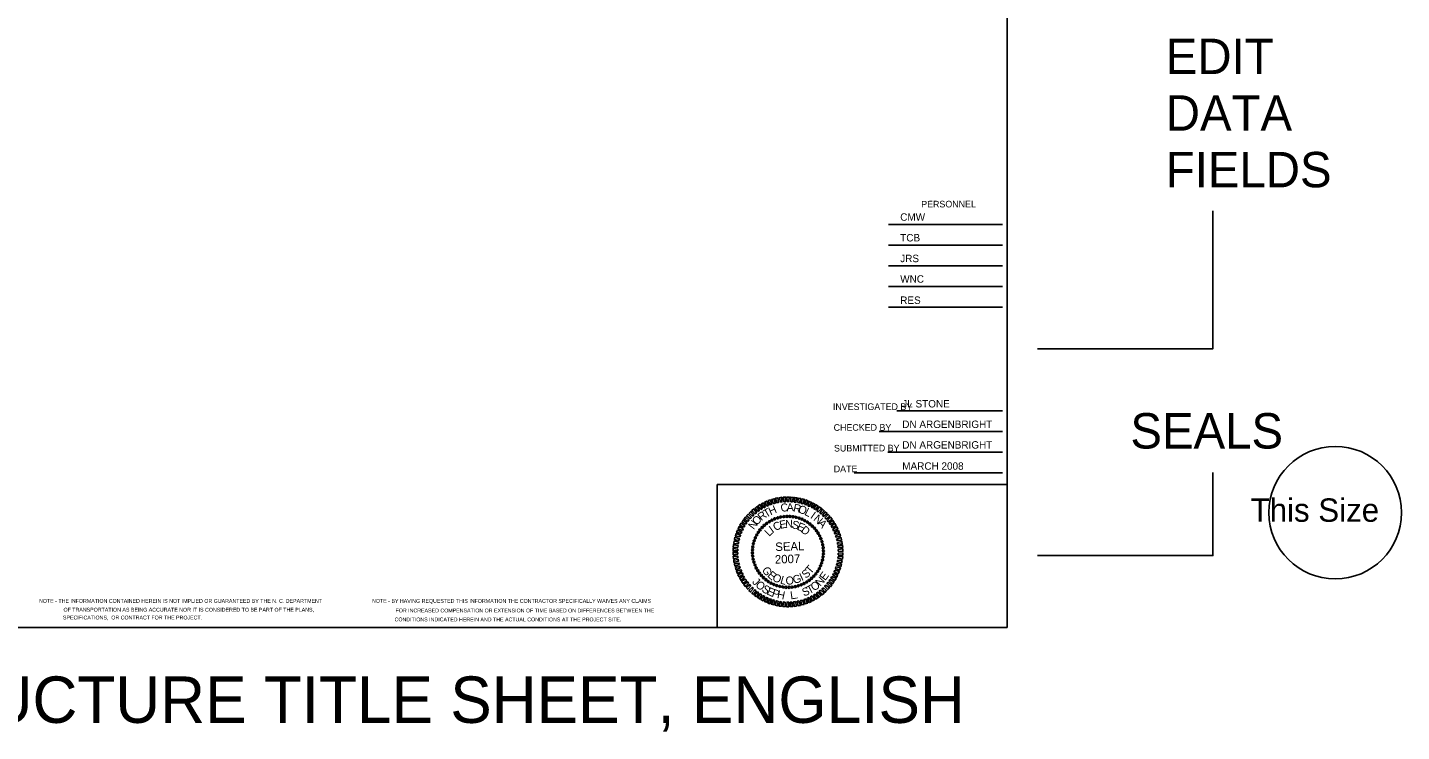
# Model space of a CAD drawing. Extents: x 278710 to 279187, y 171464 to 171625.
# Drawn here: x 278796.7 to 278951.9, y 171464.3 to 171543.9 of the extents above; entities that cross this region are included whole.
import ezdxf

# ---------------------------------------------------------------- set-up
doc = ezdxf.new("R2010")
doc.units = 0
for name, color, linetype in [('Geotech Sheets and Borders Cell', 7, 'Continuous'), ('Old_Level_2', 7, 'Continuous'), ('Old_Level_3', 7, 'Continuous'), ('Old_Level_4', 7, 'Continuous'), ('Old_Level_5', 7, 'Continuous')]:
    doc.layers.add(name, color=color, linetype=linetype)

msp = doc.modelspace()

# ---------------------------------------------------------------- linework, layer by layer
at = {"layer": 'Geotech Sheets and Borders Cell'}
for p, q in [((278893.94, 171521.62), (278906.83, 171521.62)), ((278893.94, 171519.28), (278906.83, 171519.28)), ((278893.94, 171516.94), (278906.83, 171516.94)), ((278893.94, 171514.6), (278906.83, 171514.6)), ((278893.94, 171512.26), (278906.83, 171512.26)), ((278894.89, 171500.56), (278906.83, 171500.56)), ((278892.9, 171498.21), (278906.83, 171498.21)), ((278893.87, 171495.87), (278906.83, 171495.87)), ((278890.07, 171493.53), (278906.83, 171493.53))]:
    msp.add_line(p, q, dxfattribs=at)
for points in [[(278756.09, 171580.95), (278907.34, 171580.95), (278907.34, 171476.08), (278756.09, 171476.08)], [(278907.34, 171492.21), (278874.6, 171492.21), (278874.6, 171476.08), (278907.34, 171476.08)]]:
    msp.add_lwpolyline(points, close=True, dxfattribs=at)
for points in [[(278930.6, 171523.15), (278930.6, 171507.57), (278910.78, 171507.57)], [(278930.6, 171493.58), (278930.6, 171484.19), (278910.78, 171484.19)]]:
    msp.add_lwpolyline(points, dxfattribs=at)
msp.add_circle((278944.41, 171489.04), 7.49, dxfattribs=at)
at = {"layer": 'Old_Level_2'}
for p, q in [((278879.66, 171487.36), (278879.66, 171487.36)), ((278879.9, 171487.61), (278879.9, 171487.61)), ((278880.17, 171487.82), (278880.17, 171487.82)), ((278880.47, 171488.03), (278880.47, 171488.03)), ((278880.78, 171488.19), (278880.78, 171488.19)), ((278881.1, 171488.34), (278881.1, 171488.34)), ((278881.43, 171488.45), (278881.43, 171488.45)), ((278881.77, 171488.54), (278881.77, 171488.54)), ((278882.11, 171488.6), (278882.11, 171488.6)), ((278882.47, 171488.62), (278882.47, 171488.62)), ((278882.82, 171488.62), (278882.82, 171488.62)), ((278883.16, 171488.58), (278883.16, 171488.58)), ((278883.5, 171488.52), (278883.5, 171488.52)), ((278883.85, 171488.43), (278883.85, 171488.43)), ((278884.17, 171488.3), (278884.17, 171488.3)), ((278884.48, 171488.15), (278884.48, 171488.15)), ((278884.79, 171487.96), (278884.79, 171487.96)), ((278885.08, 171487.77), (278885.08, 171487.77)), ((278885.33, 171487.54), (278885.33, 171487.54)), ((278885.59, 171487.28), (278885.59, 171487.28)), ((278878.77, 171485.87), (278878.77, 171485.87)), ((278878.9, 171486.19), (278878.9, 171486.19)), ((278879.04, 171486.51), (278879.04, 171486.51)), ((278879.24, 171486.81), (278879.24, 171486.81)), ((278879.43, 171487.1), (278879.43, 171487.1)), ((278885.81, 171487.01), (278885.81, 171487.01)), ((278886, 171486.72), (278886, 171486.72)), ((278886.16, 171486.42), (278886.16, 171486.42)), ((278886.32, 171486.1), (278886.32, 171486.1)), ((278886.43, 171485.77), (278886.43, 171485.77)), ((278878.57, 171484.49), (278878.57, 171484.49)), ((278878.58, 171484.84), (278878.58, 171484.84)), ((278878.6, 171484.13), (278878.6, 171484.13)), ((278878.61, 171485.19), (278878.61, 171485.19)), ((278878.68, 171485.53), (278878.68, 171485.53)), ((278882.59, 171484.61), (278882.59, 171484.61)), ((278886.52, 171485.43), (278886.52, 171485.43)), ((278886.57, 171485.09), (278886.57, 171485.09)), ((278886.6, 171484.73), (278886.6, 171484.73)), ((278886.6, 171484.38), (278886.6, 171484.38)), ((278878.66, 171483.79), (278878.66, 171483.79)), ((278878.74, 171483.45), (278878.74, 171483.45)), ((278878.86, 171483.12), (278878.86, 171483.12)), ((278879.01, 171482.8), (278879.01, 171482.8)), ((278886.13, 171482.71), (278886.13, 171482.71)), ((278886.27, 171483.03), (278886.27, 171483.03)), ((278886.41, 171483.34), (278886.41, 171483.34)), ((278886.49, 171483.69), (278886.49, 171483.69)), ((278886.55, 171484.04), (278886.55, 171484.04)), ((278879.17, 171482.49), (278879.17, 171482.49)), ((278879.36, 171482.21), (278879.36, 171482.21)), ((278879.58, 171481.93), (278879.58, 171481.93)), ((278879.83, 171481.68), (278879.83, 171481.68)), ((278880.09, 171481.45), (278880.09, 171481.45)), ((278880.38, 171481.25), (278880.38, 171481.25)), ((278880.68, 171481.07), (278880.68, 171481.07)), ((278884.39, 171481.02), (278884.39, 171481.02)), ((278884.7, 171481.2), (278884.7, 171481.2)), ((278884.99, 171481.39), (278884.99, 171481.39)), ((278885.26, 171481.61), (278885.26, 171481.61)), ((278885.51, 171481.86), (278885.51, 171481.86)), ((278885.74, 171482.12), (278885.74, 171482.12)), ((278885.94, 171482.41), (278885.94, 171482.41)), ((278881, 171480.92), (278881, 171480.92)), ((278881.32, 171480.79), (278881.32, 171480.79)), ((278881.66, 171480.7), (278881.66, 171480.7)), ((278882.01, 171480.64), (278882.01, 171480.64)), ((278882.36, 171480.6), (278882.36, 171480.6)), ((278882.7, 171480.6), (278882.7, 171480.6)), ((278883.06, 171480.62), (278883.06, 171480.62)), ((278883.41, 171480.68), (278883.41, 171480.68)), ((278883.75, 171480.77), (278883.75, 171480.77)), ((278884.08, 171480.88), (278884.08, 171480.88))]:
    msp.add_line(p, q, dxfattribs=at)
for points in [[(278880.21, 171489.77), (278879.97, 171490.24), (278880.2, 171490.34), (278880.39, 171489.84)], [(278880.57, 171489.92), (278880.37, 171490.4), (278880.61, 171490.48), (278880.74, 171489.99)], [(278880.96, 171490.05), (278880.76, 171490.54), (278881.04, 171490.62), (278881.13, 171490.1)], [(278881.34, 171490.16), (278881.18, 171490.66), (278881.45, 171490.7), (278881.53, 171490.19)], [(278881.73, 171490.22), (278881.62, 171490.73), (278881.88, 171490.78), (278881.91, 171490.26)], [(278882.12, 171490.28), (278882.06, 171490.8), (278882.32, 171490.81), (278882.32, 171490.28)], [(278882.51, 171490.29), (278882.47, 171490.81), (278882.74, 171490.81), (278882.7, 171490.3)], [(278882.91, 171490.28), (278882.91, 171490.81), (278883.18, 171490.77), (278883.1, 171490.27)], [(278883.28, 171490.24), (278883.35, 171490.76), (278883.6, 171490.72), (278883.48, 171490.22)], [(278883.71, 171490.17), (278883.75, 171490.69), (278884.03, 171490.65), (278883.88, 171490.14)], [(278884.08, 171490.09), (278884.18, 171490.59), (278884.44, 171490.53), (278884.26, 171490.04)], [(278884.45, 171489.97), (278884.61, 171490.48), (278884.85, 171490.38), (278884.65, 171489.92)], [(278878.32, 171488.36), (278877.91, 171488.67), (278878.09, 171488.87), (278878.46, 171488.49)], [(278878.58, 171488.66), (278878.21, 171488.99), (278878.4, 171489.18), (278878.72, 171488.77)], [(278878.88, 171488.91), (278878.52, 171489.29), (278878.73, 171489.46), (278879.04, 171489.03)], [(278879.17, 171489.17), (278878.87, 171489.56), (278879.07, 171489.73), (278879.35, 171489.27)], [(278879.51, 171489.39), (278879.19, 171489.8), (278879.44, 171489.95), (278879.66, 171489.49)], [(278879.86, 171489.59), (278879.58, 171490.02), (278879.82, 171490.15), (278880.03, 171489.68)], [(278884.83, 171489.82), (278885, 171490.31), (278885.25, 171490.2), (278885, 171489.74)], [(278885.2, 171489.66), (278885.4, 171490.12), (278885.64, 171490), (278885.35, 171489.57)], [(278885.52, 171489.46), (278885.79, 171489.93), (278886, 171489.78), (278885.7, 171489.38)], [(278885.86, 171489.24), (278886.13, 171489.69), (278886.36, 171489.52), (278886.01, 171489.14)], [(278886.19, 171489), (278886.48, 171489.44), (278886.68, 171489.25), (278886.34, 171488.89)], [(278886.48, 171488.74), (278886.8, 171489.13), (278887.01, 171488.95), (278886.6, 171488.61)], [(278886.77, 171488.46), (278887.12, 171488.84), (278887.3, 171488.64), (278886.9, 171488.31)], [(278877.44, 171487.04), (278876.98, 171487.22), (278877.07, 171487.46), (278877.52, 171487.21)], [(278877.61, 171487.39), (278877.15, 171487.61), (278877.3, 171487.85), (278877.73, 171487.55)], [(278877.84, 171487.73), (278877.4, 171487.98), (278877.53, 171488.21), (278877.93, 171487.88)], [(278878.06, 171488.04), (278877.63, 171488.34), (278877.79, 171488.54), (278878.17, 171488.2)], [(278887.03, 171488.16), (278887.4, 171488.52), (278887.57, 171488.29), (278887.14, 171488.01)], [(278887.25, 171487.84), (278887.66, 171488.17), (278887.82, 171487.94), (278887.37, 171487.69)], [(278887.48, 171487.5), (278887.9, 171487.81), (278888.03, 171487.56), (278887.57, 171487.36)], [(278887.66, 171487.17), (278888.12, 171487.42), (278888.22, 171487.19), (278887.74, 171487)], [(278876.98, 171485.53), (278876.47, 171485.57), (278876.52, 171485.84), (278877.02, 171485.71)], [(278877.05, 171485.91), (278876.55, 171486), (278876.59, 171486.27), (278877.11, 171486.09)], [(278877.15, 171486.31), (278876.65, 171486.43), (278876.75, 171486.68), (278877.23, 171486.48)], [(278877.29, 171486.67), (278876.79, 171486.83), (278876.9, 171487.08), (278877.37, 171486.85)], [(278887.82, 171486.81), (278888.29, 171487.03), (278888.39, 171486.79), (278887.9, 171486.64)], [(278887.97, 171486.42), (278888.46, 171486.63), (278888.52, 171486.37), (278888.02, 171486.26)], [(278888.07, 171486.04), (278888.58, 171486.22), (278888.63, 171485.95), (278888.14, 171485.88)], [(278888.17, 171485.66), (278888.69, 171485.8), (278888.73, 171485.53), (278888.2, 171485.47)], [(278876.91, 171484.73), (278876.38, 171484.72), (278876.38, 171485), (278876.92, 171484.93)], [(278876.92, 171484.34), (278876.39, 171484.28), (278876.38, 171484.55), (278876.91, 171484.53)], [(278876.91, 171485.12), (278876.4, 171485.14), (278876.43, 171485.42), (278876.95, 171485.32)], [(278876.94, 171483.94), (278876.42, 171483.84), (278876.4, 171484.11), (278876.91, 171484.13)], [(278888.23, 171485.28), (278888.75, 171485.37), (278888.77, 171485.11), (278888.25, 171485.09)], [(278888.25, 171484.88), (278888.79, 171484.94), (278888.79, 171484.66), (278888.27, 171484.69)], [(278888.27, 171484.48), (278888.8, 171484.5), (278888.78, 171484.23), (278888.26, 171484.29)], [(278877, 171483.56), (278876.49, 171483.42), (278876.46, 171483.69), (278876.97, 171483.75)], [(278877.1, 171483.18), (278876.59, 171483), (278876.53, 171483.27), (278877.04, 171483.34)], [(278877.2, 171482.8), (278876.72, 171482.59), (278876.65, 171482.85), (278877.14, 171482.96)], [(278877.36, 171482.41), (278876.88, 171482.18), (278876.78, 171482.43), (278877.28, 171482.58)], [(278888.01, 171482.91), (278888.51, 171482.79), (278888.42, 171482.54), (278887.94, 171482.74)], [(278888.12, 171483.3), (278888.62, 171483.21), (278888.57, 171482.95), (278888.06, 171483.13)], [(278888.21, 171483.69), (278888.71, 171483.64), (278888.65, 171483.38), (278888.16, 171483.51)], [(278888.26, 171484.1), (278888.77, 171484.07), (278888.74, 171483.8), (278888.23, 171483.9)], [(278877.52, 171482.05), (278877.06, 171481.79), (278876.94, 171482.03), (278877.43, 171482.23)], [(278877.69, 171481.71), (278877.26, 171481.41), (278877.14, 171481.66), (278877.6, 171481.86)], [(278877.93, 171481.37), (278877.51, 171481.05), (278877.35, 171481.28), (278877.8, 171481.52)], [(278878.14, 171481.05), (278877.76, 171480.7), (278877.6, 171480.92), (278878.05, 171481.21)], [(278887.11, 171481.18), (278887.55, 171480.88), (278887.38, 171480.67), (278887, 171481.03)], [(278887.33, 171481.49), (278887.77, 171481.24), (278887.63, 171481), (278887.25, 171481.33)], [(278887.55, 171481.83), (278888.02, 171481.61), (278887.88, 171481.36), (278887.44, 171481.67)], [(278887.73, 171482.18), (278888.19, 171482), (278888.09, 171481.75), (278887.64, 171482.02)], [(278887.87, 171482.55), (278888.38, 171482.39), (278888.27, 171482.14), (278887.8, 171482.37)], [(278878.4, 171480.76), (278878.05, 171480.38), (278877.87, 171480.58), (278878.27, 171480.91)], [(278878.69, 171480.48), (278878.36, 171480.08), (278878.17, 171480.26), (278878.56, 171480.6)], [(278879, 171480.22), (278878.68, 171479.78), (278878.49, 171479.96), (278878.84, 171480.32)], [(278879.31, 171479.98), (278879.03, 171479.53), (278878.81, 171479.69), (278879.15, 171480.09)], [(278879.64, 171479.76), (278879.38, 171479.29), (278879.18, 171479.44), (278879.46, 171479.85)], [(278879.97, 171479.56), (278879.78, 171479.09), (278879.53, 171479.22), (278879.81, 171479.65)], [(278880.35, 171479.4), (278880.17, 171478.91), (278879.92, 171479.01), (278880.16, 171479.47)], [(278885.31, 171479.63), (278885.59, 171479.19), (278885.36, 171479.06), (278885.14, 171479.54)], [(278885.65, 171479.83), (278885.98, 171479.41), (278885.73, 171479.27), (278885.51, 171479.73)], [(278886, 171480.05), (278886.31, 171479.66), (278886.1, 171479.49), (278885.82, 171479.95)], [(278886.29, 171480.3), (278886.66, 171479.93), (278886.44, 171479.76), (278886.13, 171480.19)], [(278886.6, 171480.56), (278886.96, 171480.23), (278886.77, 171480.03), (278886.45, 171480.45)], [(278886.85, 171480.86), (278887.27, 171480.55), (278887.09, 171480.35), (278886.72, 171480.73)], [(278880.72, 171479.26), (278880.55, 171478.75), (278880.32, 171478.83), (278880.53, 171479.3)], [(278881.08, 171479.13), (278880.98, 171478.63), (278880.74, 171478.69), (278880.91, 171479.18)], [(278881.47, 171479.05), (278881.42, 171478.52), (278881.14, 171478.57), (278881.29, 171479.08)], [(278881.87, 171478.97), (278881.84, 171478.46), (278881.57, 171478.49), (278881.69, 171478.99)], [(278882.26, 171478.93), (278882.26, 171478.41), (278881.99, 171478.44), (278882.07, 171478.95)], [(278882.67, 171478.93), (278882.7, 171478.41), (278882.43, 171478.4), (278882.48, 171478.93)], [(278883.05, 171478.94), (278883.11, 171478.42), (278882.86, 171478.42), (278882.86, 171478.94)], [(278883.45, 171479), (278883.55, 171478.49), (278883.3, 171478.44), (278883.25, 171478.97)], [(278883.83, 171479.06), (278883.99, 171478.56), (278883.73, 171478.52), (278883.64, 171479.03)], [(278884.22, 171479.16), (278884.4, 171478.67), (278884.13, 171478.61), (278884.04, 171479.13)], [(278884.59, 171479.29), (278884.79, 171478.81), (278884.55, 171478.74), (278884.42, 171479.23)], [(278884.97, 171479.44), (278885.2, 171478.98), (278884.98, 171478.87), (278884.78, 171479.38)]]:
    msp.add_lwpolyline(points, close=True, dxfattribs=at)
for centre, major_axis in [((278879.66, 171487.36), (-0.0839, 0.0789)), ((278879.91, 171487.6), (-0.0767, 0.0859)), ((278880.18, 171487.82), (-0.069, 0.0923)), ((278880.47, 171488.02), (-0.0607, 0.0979)), ((278880.78, 171488.19), (-0.052, 0.103)), ((278881.09, 171488.34), (-0.043, 0.107)), ((278881.43, 171488.45), (-0.033, 0.11)), ((278881.76, 171488.54), (-0.023, 0.113)), ((278882.11, 171488.59), (-0.014, 0.114)), ((278882.46, 171488.62), (-0.004, 0.115)), ((278882.81, 171488.62), (0.006, 0.115)), ((278883.16, 171488.58), (0.016, 0.114)), ((278883.5, 171488.52), (0.026, 0.112)), ((278883.84, 171488.42), (0.036, 0.109)), ((278884.17, 171488.3), (0.045, 0.106)), ((278884.48, 171488.14), (0.054, 0.101)), ((278884.78, 171487.97), (0.0631, 0.0964)), ((278885.07, 171487.76), (0.0713, 0.0905)), ((278885.33, 171487.53), (0.0789, 0.0839)), ((278885.58, 171487.28), (0.0859, 0.0767)), ((278878.77, 171485.86), (-0.109, 0.036)), ((278878.9, 171486.19), (-0.106, 0.045)), ((278879.05, 171486.51), (-0.101, 0.054)), ((278879.23, 171486.81), (-0.0964, 0.0631)), ((278879.43, 171487.09), (-0.0905, 0.0713)), ((278885.8, 171487.01), (0.0923, 0.069)), ((278885.99, 171486.72), (0.0979, 0.0607)), ((278886.17, 171486.42), (0.103, 0.052)), ((278886.31, 171486.1), (0.107, 0.043)), ((278886.43, 171485.77), (0.11, 0.033)), ((278878.58, 171484.84), (-0.115, 0.006)), ((278878.57, 171484.49), (-0.115, -0.004)), ((278878.6, 171484.14), (-0.114, -0.014)), ((278878.61, 171485.18), (-0.114, 0.016)), ((278878.68, 171485.53), (-0.112, 0.026)), ((278886.51, 171485.43), (0.113, 0.023)), ((278886.55, 171484.03), (0.114, -0.016)), ((278886.57, 171485.08), (0.114, 0.014)), ((278886.59, 171484.38), (0.115, -0.006)), ((278886.59, 171484.73), (0.115, 0.004)), ((278878.65, 171483.79), (-0.113, -0.023)), ((278878.74, 171483.45), (-0.11, -0.033)), ((278878.86, 171483.12), (-0.107, -0.043)), ((278879, 171482.8), (-0.103, -0.052)), ((278879.17, 171482.5), (-0.0979, -0.0607)), ((278886.12, 171482.71), (0.101, -0.054)), ((278886.27, 171483.03), (0.106, -0.045)), ((278886.39, 171483.35), (0.109, -0.036)), ((278886.49, 171483.69), (0.112, -0.026)), ((278879.37, 171482.21), (-0.0923, -0.069)), ((278879.59, 171481.94), (-0.0859, -0.0767)), ((278879.83, 171481.69), (-0.0789, -0.0839)), ((278880.1, 171481.46), (-0.0713, -0.0905)), ((278880.38, 171481.25), (-0.0631, -0.0964)), ((278880.68, 171481.07), (-0.054, -0.101)), ((278881, 171480.92), (-0.045, -0.106)), ((278884.39, 171481.03), (0.052, -0.103)), ((278884.7, 171481.2), (0.0607, -0.0979)), ((278884.99, 171481.39), (0.069, -0.0923)), ((278885.26, 171481.62), (0.0767, -0.0859)), ((278885.51, 171481.86), (0.0839, -0.0789)), ((278885.74, 171482.13), (0.0905, -0.0713)), ((278885.94, 171482.41), (0.0964, -0.0631)), ((278881.33, 171480.8), (-0.036, -0.109)), ((278881.66, 171480.7), (-0.026, -0.112)), ((278882.01, 171480.64), (-0.016, -0.114)), ((278882.36, 171480.6), (-0.006, -0.115)), ((278882.71, 171480.6), (0.004, -0.115)), ((278883.06, 171480.62), (0.014, -0.114)), ((278883.4, 171480.68), (0.023, -0.113)), ((278883.74, 171480.77), (0.033, -0.11)), ((278884.07, 171480.88), (0.043, -0.107))]:
    msp.add_ellipse(centre, major_axis=major_axis, ratio=0.999708, dxfattribs=at)

# ---------------------------------------------------------------- texts
at = {"layer": 'Geotech Sheets and Borders Cell'}
for s, height, p in [('EDIT', 4, (278925.27, 171538.61)), ('DATA', 4, (278925.27, 171532.21)), ('FIELDS', 4, (278925.27, 171525.81)), ('CMW', 0.84, (278895.27, 171522.03)), ('TCB', 0.84, (278895.27, 171519.69)), ('JRS', 0.84, (278895.27, 171517.35)), ('WNC', 0.84, (278895.27, 171515.03)), ('RES', 0.84, (278895.27, 171512.63)), ('JL STONE', 0.84, (278895.5, 171500.93)), ('SEALS', 4, (278921.27, 171496.29)), ('DN ARGENBRIGHT', 0.84, (278895.5, 171498.61)), ('DN ARGENBRIGHT', 0.84, (278895.5, 171496.28)), ('MARCH 2008', 0.84, (278895.5, 171493.89)), ('This Size', 2.64, (278934.85, 171488.01)), ('GEU STRUCTURE TITLE SHEET, ENGLISH', 5.25, (278760.97, 171465.28))]:
    msp.add_text(s, height=height, dxfattribs=at).set_placement(p)
for s, height, rotation, p in [('PERSONNEL', 0.749, 0.1322, (278897.64, 171523.53)), ('INVESTIGATED BY', 0.7488, 0.1322, (278887.67, 171500.63)), ('CHECKED BY', 0.749, 0.1322, (278887.75, 171498.29)), ('SUBMITTED BY', 0.7488, 0.1322, (278887.79, 171495.95)), ('DATE', 0.749, 0.1322, (278887.76, 171493.61)), ('NOTE - THE INFORMATION CONTAINED HEREIN IS NOT IMPLIED OR GUARANTEED BY THE N. C. DEPARTMENT', 0.4314, 359.9916, (278797.99, 171478.85)), ('OF TRANSPORTATION AS BEING ACCURATE NOR IT IS CONSIDERED TO BE PART OF THE PLANS,  ', 0.4314, 359.9916, (278800.75, 171477.86)), ('NOTE - BY HAVING REQUESTED THIS INFORMATION THE CONTRACTOR SPECIFICALLY WAIVES ANY CLAIMS', 0.4314, 359.9916, (278835.61, 171478.85)), ('FOR INCREASED COMPENSATION OR EXTENSION OF TIME BASED ON DIFFERENCES BETWEEN THE', 0.4314, 359.9916, (278838.26, 171477.77)), ('SPECIFICATIONS,  OR CONTRACT FOR THE PROJECT.', 0.4314, 359.9916, (278800.69, 171476.97)), ('CONDITIONS INDICATED HEREIN AND THE ACTUAL CONDITIONS AT THE PROJECT SITE.', 0.4314, 359.9916, (278838.15, 171476.76))]:
    msp.add_text(s, height=height, rotation=rotation, dxfattribs=at).set_placement(p)
at = {"layer": 'Old_Level_2'}
for s, height, rotation, p in [('R', 0.902, 37.7893, (278879.59, 171488.07)), ('T', 0.902, 30.5885, (278880.12, 171488.44)), ('H', 0.902, 23.3882, (278880.62, 171488.73)), ('C', 0.902, 8.9886, (278881.82, 171489.11)), ('A', 0.902, 1.7891, (278882.45, 171489.19)), ('R', 0.902, 347.3899, (278883.12, 171489.19)), ('O', 0.902, 340.1899, (278883.66, 171489.09)), ('L', 0.902, 332.9896, (278884.38, 171488.83)), ('I', 0.902, 325.7889, (278885.05, 171488.48)), ('N', 0.902, 318.5877, (278885.4, 171488.24)), ('N', 0.902, 52.1923, (278878.72, 171487.06)), ('O', 0.902, 44.9905, (278879.06, 171487.55)), ('A', 0.902, 311.3859, (278885.9, 171487.8)), ('SEAL', 0.96, 1.7688, (278881.17, 171484.7))]:
    msp.add_text(s, height=height, rotation=rotation, dxfattribs=at).set_placement(p)
at = {"layer": 'Old_Level_3'}
for s, rotation, p in [('J', 314.646, (278878.48, 171481.15)), ('O', 321.2982, (278878.84, 171480.74)), ('O', 34.4721, (278885.53, 171480.13)), ('N', 47.7764, (278886.24, 171480.66)), ('E', 54.4286, (278886.8, 171481.29)), ('S', 327.9503, (278879.54, 171480.19)), ('E', 334.6025, (278880.11, 171479.85)), ('P', 341.2547, (278880.69, 171479.59)), ('H', 347.9068, (278881.3, 171479.4)), ('L', 7.8634, (278882.9, 171479.24)), ('.', 7.8634, (278883.48, 171479.32)), ('S', 21.1677, (278884.38, 171479.56)), ('T', 27.8199, (278884.99, 171479.81))]:
    msp.add_text(s, height=0.904, rotation=rotation, dxfattribs=at).set_placement(p)
at = {"layer": 'Old_Level_4'}
for s, rotation, p in [('I', 36.1631, (278880.85, 171486.69)), ('C', 27.9518, (278881.18, 171486.93)), ('E', 11.529, (278881.72, 171487.2)), ('N', 3.3177, (278882.3, 171487.31)), ('S', 346.8949, (278882.96, 171487.3)), ('E', 338.6836, (278883.54, 171487.14)), ('D', 322.2608, (278883.96, 171486.93)), ('L', 44.3745, (278880.46, 171486.3)), ('G', 302.7403, (278879.6, 171482.58)), ('S', 41.2767, (278884.62, 171481.55)), ('T', 49.4881, (278885.15, 171482.05)), ('E', 319.163, (278880.19, 171481.86)), ('O', 335.5858, (278880.75, 171481.4)), ('L', 343.7971, (278881.65, 171481.05)), ('O', 0.2199, (278882.32, 171480.92)), ('G', 16.6426, (278883.28, 171480.98)), ('I', 24.854, (278884.14, 171481.3))]:
    msp.add_text(s, height=0.904, rotation=rotation, dxfattribs=at).set_placement(p)
at = {"layer": 'Old_Level_5'}
msp.add_text('2007', height=0.96, rotation=1.7688, dxfattribs=at).set_placement((278881.13, 171483.28))

doc.saveas('drawing.dxf')
